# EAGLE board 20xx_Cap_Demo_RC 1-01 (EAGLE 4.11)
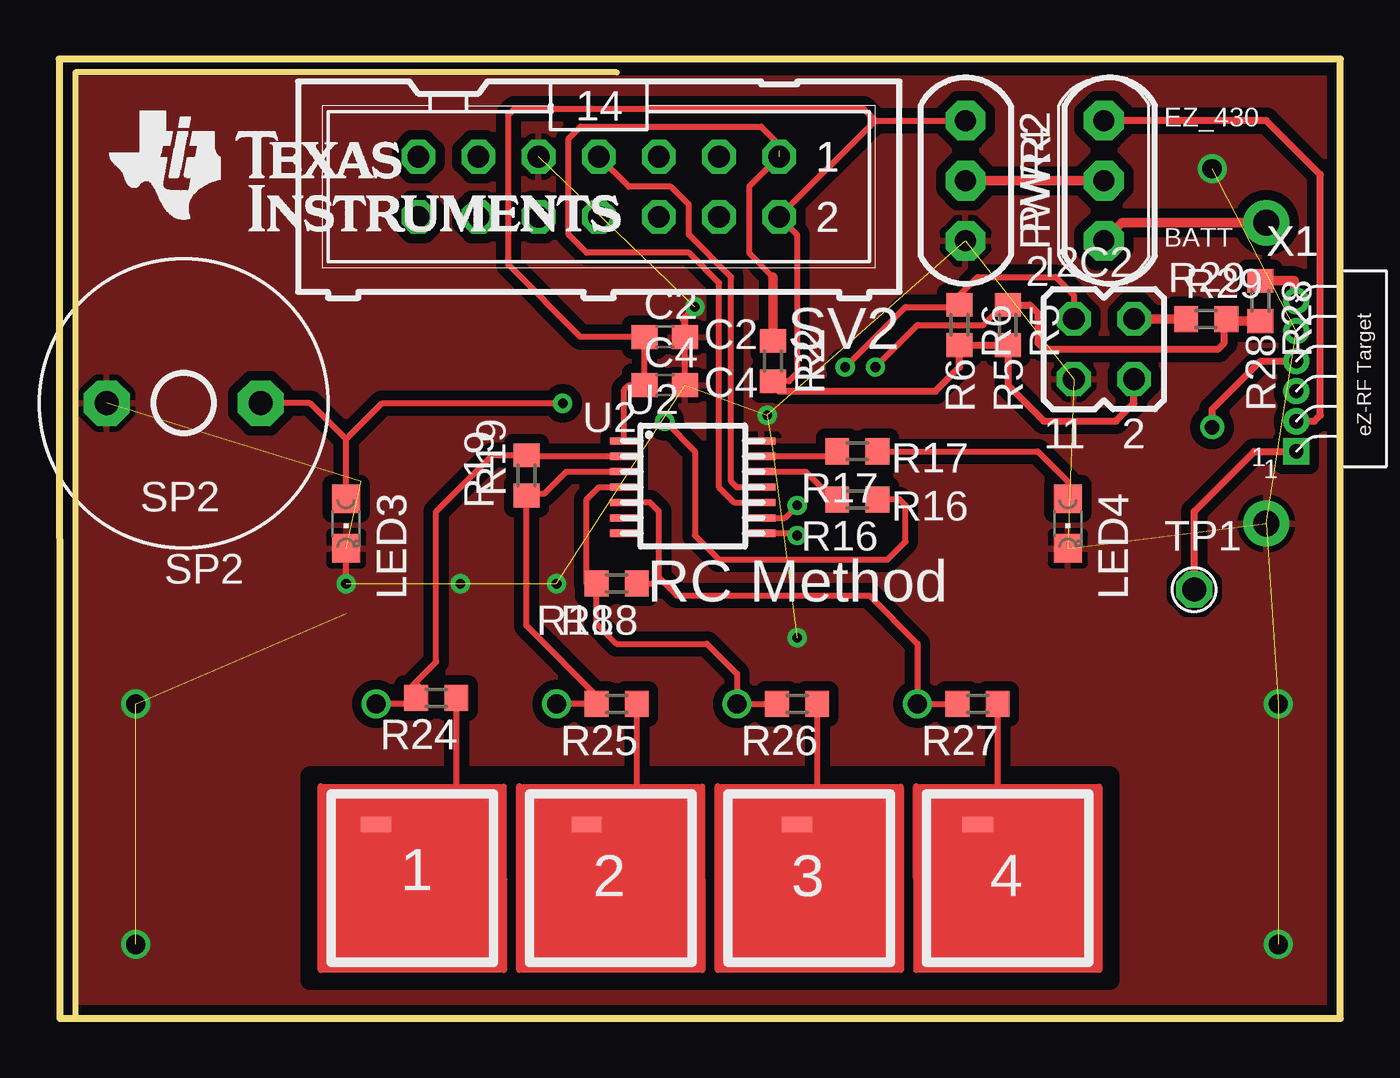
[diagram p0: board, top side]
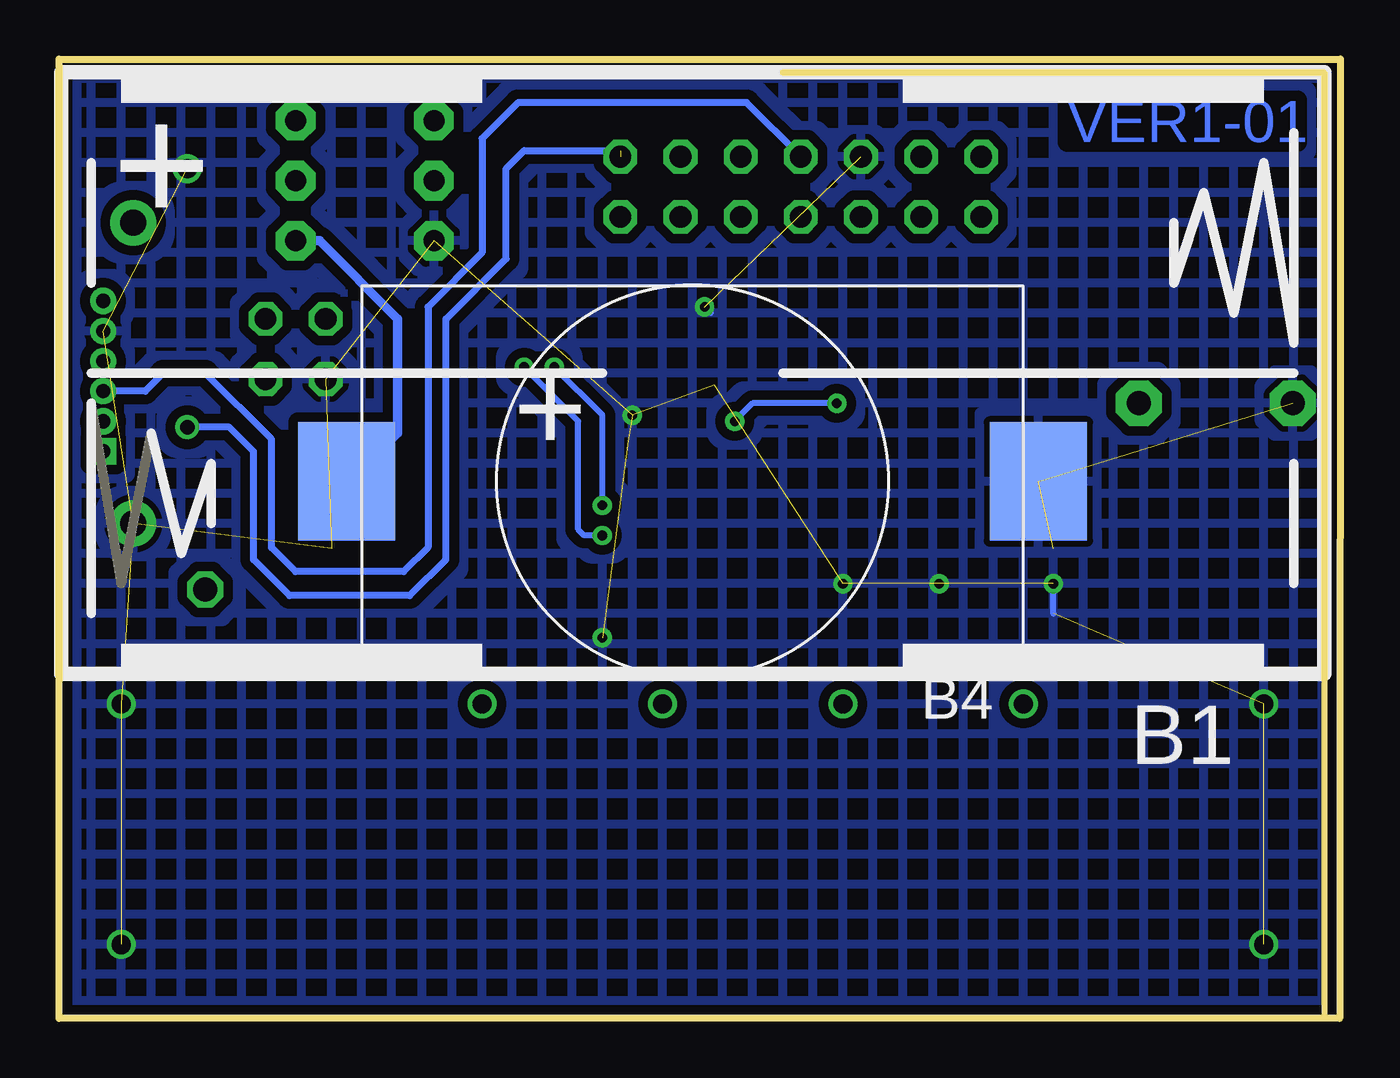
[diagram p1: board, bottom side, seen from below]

Size 54.1 x 40.51 mm. Coordinates in mm from the lower left corner, seen from the top.
Outline: 0.03,0 54.1,0 54.1,40.51 0,40.51 0.03,0
Copper layers (1*16): Top 0.035mm / dielectric 1.5mm / Bottom 0.035mm
Design rules "MSP430 PCBExpress ZA 06": minimum track width 8mil, minimum drill 14mil, track to track 8mil, track to pad 8mil, pad to pad 7mil, via to via 10mil, smd to smd 8mil, copper to edge 8mil, drill to drill 8mil, minimum pad ring 10mil, minimum via ring 8mil, stop-mask expansion 8mil, vias tented up to drill 16mil, thermal gap 10mil
Net classes: 1 Analog: width 0.254 mm, drill 0.254 mm; 2 Power: width 0.305 mm, drill 0.254 mm; 3 LCD: width 0.203 mm, drill 0.203 mm; 4 Digital: width 0.203 mm, drill 0.203 mm
Milling: 2 lines

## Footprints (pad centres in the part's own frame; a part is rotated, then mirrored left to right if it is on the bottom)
KS2468_2 = drill 1.1 pad 1.93 round: + 24.892,-6.35; - 24.892,6.35
BA2032SM = smd 4.1 x 5: + 13.97,0; - -15.24,0
C0603 = smd 1.1 x 1: 1 -0.85,0; 2 0.85,0
JP2Q = drill 0.914 octagon: 1 -1.27,-1.27; 2 -1.27,1.27; 3 1.27,-1.27; 4 1.27,1.27
CHIPLED_0805 = smd 1.2 x 1.2: A 0,-1.05; C 0,1.05
X905 = drill 0.889 pad 1.676 octagon: 1 -2.54,0; 2 0,0; 3 2.54,0
R0603 = smd 1 x 1.1: 1 -0.85,0; 2 0.85,0
AL60P = drill 1.016 pad 1.93 octagon: 1 -3.251,0; 2 3.251,0
ML14 = drill 0.914 octagon: 1 -7.62,-1.27; 2 -7.62,1.27; 3 -5.08,-1.27; 4 -5.08,1.27; 5 -2.54,-1.27; 6 -2.54,1.27; 7 0,-1.27; 8 0,1.27; 9 2.54,-1.27; 10 2.54,1.27; 11 5.08,-1.27; 12 5.08,1.27; 13 7.62,-1.27; 14 7.62,1.27
TP = drill 1.016 octagon: 1 0,0
PW14 = smd 0.3 x 1.2: 1 0.322,-1.212; 2 0.972,-1.212; 3 1.622,-1.212; 4 2.272,-1.212; 5 2.922,-1.212; 6 3.572,-1.212; 7 4.222,-1.212; 8 4.222,4.588; 9 3.572,4.588; 10 2.922,4.588; 11 2.272,4.588; 12 1.622,4.588; 13 0.972,4.588; 14 0.322,4.588
4PADSLIDERSMT = smd 1.27 x 0.635: P$1 2.54,6.35; P$2 11.43,6.35; P$3 20.32,6.35; P$4 27.94,6.35
EZ430_RF2500_6 = drill 0.6 pad 1.016 square: 1 0,0 | drill 0.6 pad 1.016 round: 2 0,1.27; 3 0,2.54; 4 0,3.81; 5 0,5.08; 6 0,6.35

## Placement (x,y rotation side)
B1  [KS2468_2]  26.09,27.25 180 bottom
B4  3V  [BA2032SM]  27.99,22.68 180 bottom
C2  0.1uF  [C0603]  25.58,28.78 0 top
C4  1u  [C0603]  25.58,26.75 0 top
I2C2  [JP2Q]  44.12,28.27 0 top
LED3  [CHIPLED_0805]  12.12,20.9 180 top
LED4  [CHIPLED_0805]  42.6,20.9 180 top
PWR2  [X905]  38.28,35.38 270 top
PWR4  [X905]  44.12,35.38 90 top
R2  47k  [R0603]  30.15,27.76 270 top
R5  10k  [R0603]  40.06,29.29 270 top
R6  10k  [R0603]  38.02,29.29 270 top
R16  499  [R0603]  33.71,21.92 180 top
R17  499  [R0603]  33.71,23.95 180 top
R18  5M1  [R0603]  23.55,18.36 180 top
R19  5M1  [R0603]  19.74,22.94 90 top
R24  0  [R0603]  15.93,13.54 180 top
R25  0  [R0603]  23.55,13.28 180 top
R26  0  [R0603]  31.17,13.28 180 top
R27  0  [R0603]  38.79,13.28 180 top
R28  0  [R0603]  50.72,30.3 270 top
R29  0  [R0603]  48.44,29.54 0 top
SP2  AL60P  [AL60P]  5.26,25.98 180 top
SV2  [ML14]  22.78,35.13 180 top
TP1  [TP]  47.93,18.11 0 top
U2  F20XX  [PW14]  25.07,24.71 270 top
U$6  4PADSLIDER  [4PADSLIDERSMT]  10.85,1.85 0 top
U$7  [TI_LOGO_NEW2]  1.7,32.08 0 top
X1  [EZ430_RF2500_6]  52.25,23.95 0 top

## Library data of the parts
B1 R2 R5 R6 R16-R19 R24-R29 = _MSP430
B4 LED3 LED4 PWR2 PWR4 SV2 U2 = F20xx PIR Demo & Eval
C2 C4 = rcl
I2C2 = jumper
SP2 = buzzer
TP1 = _5438_ATC
U$6 = Touch Pad
U$7 = _ti_logo
X1 = _MSP430_RF

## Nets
EZ430_PWR: PWR4.3 X1.2
GND: B1.- B4.- C2.2 C4.2 I2C2.1 LED3.C LED4.C PWR2.3 SP2.2 SV2.9 U2.14 X1.5
N$3: LED3.A R16.1 SP2.1
N$5: LED4.A R17.1
N$9: R24.1 U$6.P$1
N$10: R25.1 U$6.P$2
N$11: R26.1 U$6.P$3
N$12: R27.1 U$6.P$4
N$13: R28.1 X1.6
N$14: I2C2.4 R29.1
N$16: TP1.1 X1.1
N$19: R16.2 U2.12
N$20: R17.2 U2.13
N$26: PWR2.2 PWR4.2
P1.0: R19.2 R24.2 U2.2
P1.1: R19.1 R25.2 U2.3
P1.2: R18.2 R26.2 U2.4
P1.3: R18.1 R27.2 U2.5
SBWCLK1: SV2.7 U2.11 X1.3
SBWDAT1: R2.1 SV2.1 U2.10 X1.4
SCL_2: R5.1 R28.2 R29.2 U2.8
SDA_2: I2C2.2 R6.1 U2.9
VBATT: B1.+ B4.+ PWR4.1
VCC: C2.1 C4.1 I2C2.3 PWR2.1 R2.2 R5.2 R6.2 SV2.2 U2.1

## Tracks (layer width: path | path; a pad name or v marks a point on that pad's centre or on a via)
EZ430_PWR
  Top 0.305: X1.2 53.01,25.22 53.26,25.48 53.26,35.64 50.98,37.92 PWR4.3 43.87,37.92
GND  (via drill 0.41, 0.81)  (19 unrouted)
  Top 0.254: 26.43,28.44 26.34,28.52 26.43,28.61 C2.2 | v26.85,30.05 26.43,29.63 26.43,29.54 C2.2 | 30.08,24.39 U2.14 | C4.2 C2.2 | v12.12,18.36 LED3.C
  Top 0.305: 26.43,29.54 26.34,29.54 26.43,29.45 C2.2
  Bottom 0.254: v26.85,30.05 26.59,29.79 | 12.12,17.09 v12.12,18.36
  other vias: 51.49,3.12 48.69,35.89 51.49,13.28 31.17,16.08 29.9,25.48 21.01,18.36 16.94,18.36 3.23,13.28 3.23,3.12
  pour Bottom (isolate 0.406, hatched): 0.43,39.7 0.43,0.58 53.52,0.58 53.52,39.7
  pour Top (isolate 0.406): 0.43,0.58 0.43,39.7 53.52,39.7 53.52,0.58
  pour Top (isolate 0.406): 0.43,0.58 0.43,39.7 53.52,39.7 53.52,0.58
N$3  (via drill 0.41)
  Top 0.254: R16.1 35.48,21.92 35.74,21.67 35.74,20.14 34.98,19.38 27.86,19.38 26.85,20.4 26.85,23.95 v25.58,25.22 | v21.26,25.98 13.64,25.98 12.12,24.46 | LED3.A 12.12,24.46 | SP2.1 10.59,25.98 12.12,24.46
  Bottom 0.254: v21.26,25.98 24.82,25.98 v25.58,25.22
N$5
  Top 0.254: R17.1 41.33,23.95 42.6,22.68 LED4.A
N$9
  Top 0.254: 14.91,8.2 15.93,8.2 | 14.91,8.2 14.66,8.46 16.43,8.46 | 16.43,8.46 16.69,8.71 | 16.43,8.46 16.78,8.8 R24.1 | U$6.P$1 14.91,8.2
N$10
  Top 0.254: 22.53,8.71 22.78,8.97 23.55,8.97 22.78,8.2 U$6.P$2 | 22.53,8.71 22.28,8.46 | 22.53,8.71 23.8,8.46 24.4,9.05 R25.1
N$11
  Top 0.254: U$6.P$3 30.4,8.2 30.15,8.46 31.67,8.71 32.02,9.05 R26.1
N$12
  Top 0.254: U$6.P$4 37.52,8.71 37.77,8.97 39.29,8.2 39.64,8.55 R27.1
N$13
  Top 0.406: R28.1 52.16,31.15 X1.6
N$14
  Top 0.305: 47.42,29.54 R29.1
  Top 0.406: I2C2.4 47.42,29.54
N$16
  Top 0.305: TP1.1 47.93,21.41 50.47,23.95 X1.1
N$19
  Top 0.254: U2.12 31.52,23.09 32.69,21.92 R16.2
N$20
  Top 0.254: U2.13 32.73,23.74 32.94,23.95 R17.2
N$26
  Top 0.406: PWR2.2 PWR4.2
P1.0  (via drill 0.81)
  Top 0.254: U2.2 20.03,23.74 19.99,23.7 19.9,23.79 R19.2 18.3,23.79 15.93,21.41 15.93,15.06 14.91,14.05 R24.2 | R24.2 15,13.63 14.91,13.28 v13.39,13.28 | R24.2 15.16,14.05
P1.1  (via drill 0.81)
  Top 0.254: U2.3 21.42,23.09 20.5,22.17 19.99,22.17 19.9,22.09 R19.1 | R19.1 19.57,22.09 19.48,22.17 | 21.09,13.37 v21.01,13.28 R25.2 22.78,13.54 19.74,16.59 R19.1
P1.2  (via drill 0.81)
  Top 0.254: U2.4 22.8,22.44 22.28,21.92 22.28,18.36 R18.2 22.7,16.67 23.55,15.82 27.36,15.82 28.63,14.55 v28.63,13.28 28.71,13.37 28.63,13.54 28.88,13.28 R26.2
P1.3  (via drill 0.81)
  Top 0.254: U2.5 24.94,21.79 25.32,21.41 25.32,18.62 | 25.32,18.62 25.07,18.36 R18.1 | v36.25,13.28 R27.2 | v36.25,13.28 36.33,13.37 | 25.32,18.62 26.09,17.86 34.21,17.86 36.25,15.82 v36.25,13.28
SBWCLK1
  Top 0.254: U2.11 28.61,22.44 28.37,22.68 28.37,31.32 26.59,33.1 26.59,34.37 25.83,35.13 24.05,35.13 SV2.7
  Bottom 0.305: SV2.7 25.07,38.68 34.72,38.68 36.25,37.16 36.25,32.33 38.53,30.05 38.53,19.89 39.55,18.87 44.12,18.87 45.14,19.89 45.14,24.46 47.93,27.25 49.71,27.25 50.47,26.49 X1.3
SBWDAT1  (via drill 0.61)  (1 unrouted)
  Top 0.254: U2.10 28.5,21.79 27.86,22.43 27.86,31.06 26.59,32.33 22.28,32.33 21.51,33.1 21.51,37.16 22.02,37.67 29.64,37.67 30.4,36.91 SV2.1 29.13,35.13 29.13,32.33 30.15,31.32
  Top 0.305: X1.4 50.72,27.76 48.69,25.73 v48.69,24.97
  Top 0.406: 30.15,31.32 R2.1
  Bottom 0.305: 30.4,36.65 34.47,36.65 35.23,35.89 35.23,32.08 37.77,29.54 37.77,19.38 39.29,17.86 44.37,17.86 45.9,19.38 45.9,23.95 46.91,24.97 v48.69,24.97
SCL_2  (via drill 0.41)
  Top 0.254: U2.8 31.07,20.49 v31.17,20.4 | v34.47,27.51 36.25,29.29 39.04,29.29 39.89,30.14
  Top 0.305: 49.2,29.54 49.2,28.52 48.95,28.27 41.58,28.27 41.33,28.52 41.33,29.79 40.98,30.14 R5.1 40.06,30.05 39.97,30.14 39.89,30.14
  Top 0.406: R29.2 49.2,29.54 49.29,29.45 R28.2
  Bottom 0.254: v31.17,20.4 31.93,20.4 32.18,20.65 32.18,25.22 v34.47,27.51
SDA_2  (via drill 0.41)
  Top 0.254: U2.9 30.64,21.14 v31.17,21.67 | v33.2,27.51 35.74,30.05 38.02,30.05 38.11,30.14 R6.1 38.02,30.56 38.79,31.32 42.09,31.32 42.85,30.56 I2C2.2
  Bottom 0.254: v31.17,21.67 31.17,25.48 v33.2,27.51
VBATT
  Top 0.406: B1.+ 44.88,33.6 PWR4.1
  Bottom 0.406: B4.+ 41.83,22.68 39.8,24.71 39.8,29.54 43.1,32.84 PWR4.1
VCC
  Top 0.254: R2.2 30.82,26.91 31.17,27.25 31.17,33.1 SV2.2 34.47,37.92 | 34.47,37.92 PWR2.1 | 34.47,37.92 33.96,38.43 19.23,38.43 18.97,38.18 18.97,31.83 22.02,28.78 C2.1 24.73,26.66 | C4.1 24.82,26.75 24.73,26.66 | 24.73,26.66 24.56,26.75 24.05,26.75 23.86,26.55 U2.1
  Top 0.305: I2C2.3 45.39,25.98 44.63,25.22 41.58,25.22 40.06,26.75 R5.2 | R5.2 40.06,28.52 | R5.2 38.11,28.44 38.02,28.52 R6.2 38.02,27.51 37.01,26.49 30.4,26.49 30.15,26.75 R2.2

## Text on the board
Bottom: VER1-01
_tplace: PWR2 | EZ_430 | 1 | 2 | BATT | X1 | R29 | 2 | C2 | R28 | C4 | R2 | R6 | R5 | U2 | R17 | 1 | SP2 | LED3 | R16 | LED4 | 1 | R19 | R18 | RC Method | R24 | R25 | R26 | R27 | 1 | 2 | 3 | 4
